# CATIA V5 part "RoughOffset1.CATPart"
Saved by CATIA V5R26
Part number: Part2
Bounding box of the stored display mesh (mm): x -142.587 to 50, y -60 to 170, z -56 to 80
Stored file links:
  D:\_Deepak\CATIA\CATIA V5-6R2016_Deepak\Resources\Part files\Partfiles\c18_catia_v6_6r2016_prt\RoughOffset1.CATPart
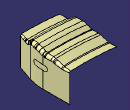
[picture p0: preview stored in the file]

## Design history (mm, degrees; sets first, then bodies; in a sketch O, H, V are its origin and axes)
Set1
  DatumSurface1
  DatumSurface2
  Sketch1 on xy-plane, origin (0, 0, 0), H (1, 0, 0), V (0, 1, 0)
    line L1 (180, 0) -> (420, 0)
    point P1 (180, 0)
    coincidence: P1 H
    horizontal: L1 H
  Point1: type OnPlane, Support xy-plane, H 200, V 5, Direction (1, 0, 0)
  Point2: type OnPlane, Support xy-plane, H 250, V 10, Direction (1, 0, 0)
  Point3: type OnPlane, Support xy-plane, H 320, V 13, Direction (1, 0, 0)
  Point4: type OnPlane, Support xy-plane, H 380, V 6, Direction (1, 0, 0)
  Point5: type OnPlane, Support xy-plane, H 400, V 5, Direction (1, 0, 0)
  LineCorner1: Elements (Point1; {linecornerpoint Pt Point2, Radius 60}; {linecornerpoint Pt Point3, Radius 55}; {linecornerpoint Pt Point4, Radius 80}; Point5)
  LawDistProj1: Reference Sketch1, Definition LineCorner1
  Intersect1: ToIntersect1 DatumSurface1, ToIntersect2 DatumSurface2
  CurvePar1: Length LawDistProj1, Offset Intersect1, Support DatumSurface1
  Point6: type OnCurve, Support Intersect1, Length 0
  Point7: type OnCurve, Support Intersect1, Length 48.6659 {= length(Intersect1) / 5}
  Point8: type OnCurve, Support Intersect1, Length 97.3318 {= (length(Intersect1)) * 2 / 5}
  Point9: type OnCurve, Support Intersect1, Length 145.9977 {= (length(Intersect1)) * 3 / 5}
  Point10: type OnCurve, Support Intersect1, Length 194.6636 {= (length(Intersect1)) * 4 / 5}
  Point11: type OnCurve, Support Intersect1, Length 243.3295 {= length(Intersect1)}
  Curve1: Elements (Point11; Point10; Point9; Point8; Point7; Point6)
  Fillet1: type BiTangent, Element1 DatumSurface2, Element2 DatumSurface1, Radius 25, Spine Curve1, HoldCurve CurvePar1
  Boundary1: Boundary Fillet1
  Split1: ToCut DatumSurface1, Cutting Boundary1
  Split2: ToCut DatumSurface2, Cutting Boundary1
  Join1: Elements (Split2; Fillet1; Split1)
  Offset1: Offset DatumSurface1, Length 20
  Offset2: Offset DatumSurface2, Length 20
  Trim1: Element1 Offset2, Element2 Offset1
  Fill1: Boundary ({fillboundary BoundaryWire edge of DatumSurface2, Support Join1}; {fillboundary BoundaryWire edge of DatumSurface2, Support Join1})
  Join2: Elements (Fill1; Join1)
Body1 (main body)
